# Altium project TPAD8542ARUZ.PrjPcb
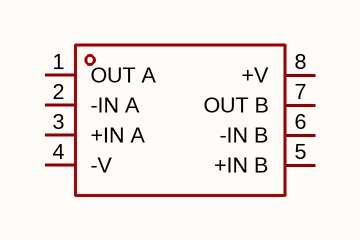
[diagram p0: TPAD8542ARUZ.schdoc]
1 sheet, 1 parts. Net scope: global (net labels, ports and power ports of the same name join across sheets).

## Sheet TPAD8542ARUZ.schdoc
size 127 x 101 mm

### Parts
U?  tpad8542aruz  [TSSOP-8_L4.4-W3.0-P0.65-LS6.4-BL-3]  (value not drawn)

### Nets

Not connected (* = marked no-connect by the designer): U? 1(OUT_A) 2(-IN_A) 3(+IN_A) 4(-V) 5(+IN_B) 6(-IN_B) 7(OUT_B) 8(+V)

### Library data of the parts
U? = tpad8542aruz: 放大器数:2;轨到轨:轨到轨输入,轨到轨输出;增益带宽积(GBW):1MHz;输入失调电压(Vos):500uV;压摆率(SR):-;输入偏置电流(Ib):10pA;; Manufacturer: TECH PUBLIC(台舟); AddInBom: yes; ModelId: 03fc033f402846a5ab66f50ee4246a8b; ModelTransform: 118.11,251.968,0,0,0,0,0,0,0; Number of Channels: 2; Gain Bandwidth Product: 1MHz; Vos - Input Offset Voltage: 500uV; Input Offset Voltage Drift(Vos TC): 650nV/℃; Ib - Input Bias Current: 10pA; Common Mode Rejection Ratio(CMRR): 95dB; Quiescent Current: 50uA; Output Current: 20mA; Single supply: 2.1V~5.5V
